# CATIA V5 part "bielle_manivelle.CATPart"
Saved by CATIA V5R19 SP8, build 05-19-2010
Part number: bielle_manivelle
Bounding box of the stored display mesh (mm): x 76 to 83, y -10.289 to 49.743, z 53.46 to 76.834
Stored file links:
  G:\EU_thinkMotion\CFAO_2010\MMS_groupe3\MMS_groupe3\A reprendre\amenand\amenand\bielle_manivelle.CATPart
  F:\thinkmotion CFAO v12.1\essuie_glace.CATProduct
  G:\EU_thinkMotion\CFAO_2010\MMS_groupe3\MMS_groupe3\A reprendre\amenand\amenand\squelette_bati.CATPart
  G:\EU_thinkMotion\CFAO_2010\MMS_groupe3\MMS_groupe3\A reprendre\amenand\amenand\squelette_bielle.CATPart
  G:\EU_thinkMotion\CFAO_2010\MMS_groupe3\MMS_groupe3\A reprendre\amenand\amenand\squelette_bielle_manivelle.CATPart
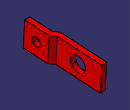
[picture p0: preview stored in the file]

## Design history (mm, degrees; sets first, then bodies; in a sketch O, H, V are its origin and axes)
Set1
  Plane1: linked copy from another document
  Plane2: linked copy from another document
  Line1: linked copy from another document
  Point1: linked copy from another document
  Plane3: linked copy from another document
  Point2: linked copy from another document
Body1 (main body)
  Sketch1 on Plane2, origin (83, 0, 0), H (0, 1, 0), V (0, 0, 1)
    line L1 (-9.1335, 76.8342) -> (-10.2892, 56.8676)
    line L2 (-10.2892, 56.8676) -> (48.5874, 53.4598)
    line L3 (48.5874, 53.4598) -> (49.7431, 73.4264)
    line L4 (49.7431, 73.4264) -> (-9.1335, 76.8342)
    reference projected line E1 (0.0847, 66.2839) -> (30.629, 64.516) from Line1
    reference projected point E2 (-9.7113, 66.8509) from Sketch2.L1
    reference projected point E3 (49.1652, 63.4431) from Sketch2.L5
    distance E1 L4 = 10
    distance L4 L2 = 20
    perpendicularity: L1 L2
    coincidence: L1 E2, L3 E3
  Sketch2 on Plane1, origin (0, 3.824, 66.0675), H (1, 0, 0), V (0, -0.9983, 0.0578)
    line L1 (78.8932, 13.558) -> (83, 13.558)
    line L2 (78.8932, 13.558) -> (78.8932, -4.708)
    line L3 (78.8932, -4.708) -> (76, -8.3612)
    line L4 (76, -8.3612) -> (76, -45.4171)
    line L5 (76, -45.4171) -> (80.1068, -45.4171)
    line L6 (80.1068, -45.4171) -> (80.1068, -9.7909)
    line L7 (80.1068, -9.7909) -> (83, -6.1376)
    line L8 (83, -6.1376) -> (83, 13.558)
    reference intersected line E1 through (83, 0) direction (0, 1) from Plane2
    reference intersected line E2 through (76, 0) direction (0, 1) from Plane3
    distance L8 L2 = 4.1068
    distance L4 L6 = 4.1068
    length L6 = 35.6263
    distance L7 L3 = 4.107
    horizontal: L1 H, L5 H
    vertical: L2 V, L4 V, L6 V
    coincidence: L8 E1, L4 E2
  SolidCombine1: FirstComponentProfile Sketch1, FirstComponentDirection Sketch1, SecondComponentProfile Sketch2, SecondComponentDirection Sketch2
  Sketch3 on face of SolidCombine1 from Sketch2.L2, origin (78.8932, 0.2798, 73.8098), H (0, 1, 0), V (0, 0, -1)
    point P1 (-0.1951, 7.5259)
    reference projected point E1 (-0.1951, 7.5259) from Point1
    coincidence: P1 E1
  Hole1: placed by Sketch3, at (78.8932, 0.0847, 66.2839) direction (1, 0, 0), diameter 7, through (limit type 6)
  Sketch4 on face of SolidCombine1 from Sketch2.L4, origin (76, 38.4272, 67.1486), H (0, 1, 0), V (0, 0, -1)
    point P1 (-7.7982, 2.6326)
    reference projected point E1 (-7.7982, 2.6326) from Point2
    coincidence: E1 P1
  Hole2: placed by Sketch4, at (76, 30.629, 64.516) direction (1, 0, 0), diameter 12, through (limit type 6)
